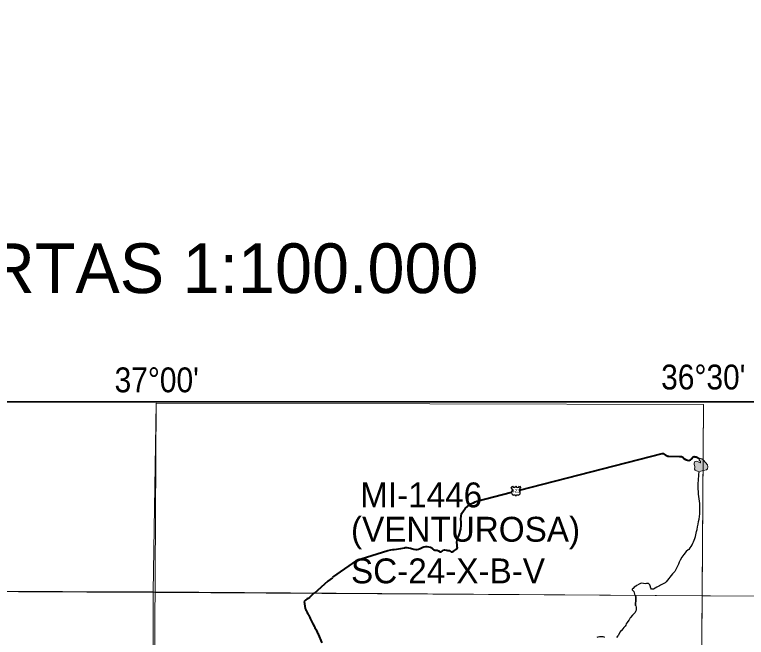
# Model space of a CAD drawing. Extents: x -1643653 to 4543381, y 1624270 to 13878484.
# Drawn here: x 604813 to 619526, y 8920034 to 8932559 of the extents above; entities that cross this region are included whole.
import ezdxf
from ezdxf.enums import TextEntityAlignment as Align

# ---------------------------------------------------------------- set-up
doc = ezdxf.new("R2010")
doc.units = 0
doc.header["$LTSCALE"] = 200
doc.layers.add('1', color=7, linetype='Continuous', lineweight=13)
doc.layers.add('6', color=7, linetype='Continuous', lineweight=13)

msp = doc.modelspace()

# ---------------------------------------------------------------- hatches: boundary and pattern name
at = {"layer": '6'}
msp.add_hatch(color=256, dxfattribs=at).paths.add_polyline_path([(618590.4, 8923622.6), (618579.9, 8923599.2), (618603.3, 8923569.1), (618601.9, 8923550), (618595.2, 8923541.4), (618555.1, 8923567.6), (618516.4, 8923579.6), (618490.1, 8923569.1), (618473.9, 8923540.4), (618479.6, 8923509.8), (618492, 8923472.6), (618488.2, 8923448.2), (618485.8, 8923418.6), (618496.8, 8923398.6), (618526.4, 8923383.3), (618561.3, 8923372.8), (618610, 8923374.2), (618666.8, 8923390.9), (618723.7, 8923405.7), (618745.6, 8923421), (618754.2, 8923461.6), (618742.3, 8923501.7), (618701.7, 8923551.9), (618664, 8923597.7), (618633.9, 8923625.4), (618610.5, 8923632.6)])

# ---------------------------------------------------------------- linework, layer by layer
at = {"layer": '1', "lineweight": 25}
msp.add_spline([(814781, 9009175.5), (814787.2, 9009173.4), (814796.9, 9009173.4), (814799.4, 9009172.4), (814805.1, 9009174.5), (814805.6, 9009176.5), (814811.7, 9009179.5), (814811.7, 9009179.5), (814801.5, 9009181), (814790.7, 9009181.5), (814784.1, 9009183.1), (814777.4, 9009185.1), (814778.4, 9009175.5)], degree=3, dxfattribs=at)
at = {"layer": '6', "lineweight": 25}
for p, q in [((614790.2, 8923043.1), (614822.1, 8923075.1)), ((614962, 8923075.1), (614994, 8923043.1))]:
    msp.add_line(p, q, dxfattribs=at)
at = {"layer": '6', "lineweight": 35}
msp.add_lwpolyline([(574695.3, 8924769.6), (626625.7, 8924769.6), (626625.7, 8896026.7), (574695.3, 8896026.7)], close=True, dxfattribs=at)
at = {"layer": '6'}
for points in [[(607657.7, 8924743.3), (607574.2, 8909874.9), (607492.3, 8896026.7)], [(618663, 8924716.1), (618558.3, 8909803.7), (618456.5, 8896026.7)], [(574684.9, 8921064.7), (596639.8, 8920989.8), (607636.3, 8920937.2), (626625.7, 8920820.5)]]:
    msp.add_lwpolyline(points, dxfattribs=at)
for points in [[(607657.7, 8924743.3), (618663, 8924716.1), (618636, 8920869.6), (607600.8, 8920952.4)], [(618590.4, 8923622.6), (618579.9, 8923599.2), (618603.3, 8923569.1), (618601.9, 8923550), (618595.2, 8923541.4), (618555.1, 8923567.6), (618516.4, 8923579.6), (618490.1, 8923569.1), (618473.9, 8923540.4), (618479.6, 8923509.8), (618492, 8923472.6), (618488.2, 8923448.2), (618485.8, 8923418.6), (618496.8, 8923398.6), (618526.4, 8923383.3), (618561.3, 8923372.8), (618610, 8923374.2), (618666.8, 8923390.9), (618723.7, 8923405.7), (618745.6, 8923421), (618754.2, 8923461.6), (618742.3, 8923501.7), (618701.7, 8923551.9), (618664, 8923597.7), (618633.9, 8923625.4), (618610.5, 8923632.6)], [(607600.8, 8920952.4), (596639.8, 8920989.8), (596608.8, 8909934.4), (607569.8, 8909894.9)], [(618636, 8920869.6), (626625.7, 8920820.5), (626625.7, 8909822.1), (618558.7, 8909851.2)]]:
    msp.add_lwpolyline(points, close=True, dxfattribs=at)
at = {"layer": '6', "lineweight": 40}
for points in [[(614964.2, 8922992.9), (617832.6, 8923732.6), (617846.7, 8923732.8), (617858.9, 8923730.9), (617871.2, 8923721), (617893.7, 8923707.2), (617921.3, 8923691.5), (617934.6, 8923682.6), (617949.8, 8923677.8), (617965, 8923676), (618178.8, 8923671.4), (618220.3, 8923669), (618246.8, 8923657.3), (618269.5, 8923633.4), (618301.1, 8923613.7), (618341.8, 8923600.2), (618367.2, 8923594.5), (618405.5, 8923607.3), (618420.6, 8923616.6), (618432.5, 8923630.9), (618446.4, 8923654.4), (618458.4, 8923663.7), (618473.5, 8923670), (618492.7, 8923668.3), (618517.1, 8923664.6), (618591.3, 8923622.3)], [(611214.5, 8921246.7), (611690.9, 8921581.7), (611739.2, 8921604.7), (611780.6, 8921615.4), (612315.8, 8921783.7), (612380.5, 8921791.8), (612418.8, 8921801.5), (612446.2, 8921801.9), (612579.5, 8921823.3), (612649.2, 8921836.5), (612665.4, 8921838.8), (612696.8, 8921839.3), (612734.3, 8921834.8), (612769.8, 8921828.3), (612794.3, 8921820.6), (612836.9, 8921811.2), (612878.6, 8921802.8), (612904.9, 8921800.2), (612931.2, 8921805.6), (612968.5, 8921819.4), (612991.5, 8921833.9), (613020.7, 8921847.5), (613043.9, 8921853.9), (613078.2, 8921864.6), (613100.5, 8921863.9), (613172.6, 8921848.9), (613187.9, 8921842.1), (613203.2, 8921832.2), (613213.5, 8921824.3), (613217.6, 8921816.3), (613223.8, 8921806.3), (613239.2, 8921795.4), (613263.6, 8921790.7), (613283.8, 8921790), (613306.2, 8921786.3), (613333.6, 8921777.7), (613370.4, 8921757.1), (613391.7, 8921751.3), (613410.8, 8921764.8), (613432.7, 8921788.4), (613459, 8921792.8), (613487.4, 8921786.2), (613506.7, 8921785.5), (613523.9, 8921782.7), (613547.3, 8921778.1), (613567.7, 8921770.3), (613590.2, 8921755.5), (613610.5, 8921752.8), (613631.6, 8921763.2), (613655.6, 8921783.8), (613674.6, 8921799.3), (613688.6, 8921808.6), (613703.7, 8921814.9), (613713.7, 8921824.2), (613717.6, 8921837.4), (613713.3, 8921852.5), (613712.8, 8921885.8), (613707.8, 8921948.4), (613715.8, 8922026.4), (613743.5, 8922073.3), (613761, 8922118.1), (613780.1, 8922192.2), (613785.2, 8922213.2), (613792, 8922289.4), (613792.2, 8922338.9), (613787.9, 8922425.8), (613790.3, 8922468.3), (613797.6, 8922523), (613826.5, 8922560.8), (613869.1, 8922624.2), (613980.1, 8922716.9), (614036.5, 8922740.1), (614074.7, 8922760.9), (614109.9, 8922772.6), (614804.5, 8922951.7)], [(611201.4, 8921234.4), (611108.7, 8921166), (610832.8, 8920916.1)], [(610827.8, 8920917.6), (610823, 8920914), (610762.1, 8920855.7), (610749.5, 8920841.5), (610740.9, 8920836.9), (610713, 8920816.2), (610698.2, 8920806.3), (610662.6, 8920780.4), (610653.5, 8920774.9), (610648.2, 8920770.6), (610634.6, 8920757.1)], [(610634.6, 8920757.1), (610655.2, 8920612.5), (610665.4, 8920591.1), (610678.2, 8920567.9), (610682, 8920558.9), (610694.4, 8920535.7), (610709.7, 8920504), (610719.3, 8920486.7), (610726, 8920471.9), (610739.4, 8920447.4), (610745.8, 8920433.2), (610758.2, 8920410.6), (610809.7, 8920308.8), (610840.7, 8920249.1), (610850, 8920232.8), (610852.7, 8920225.4), (610867.4, 8920199.1), (610898.1, 8920137.8), (610910.3, 8920115.9), (610916.7, 8920101.6), (610989.7, 8919925.2)]]:
    msp.add_lwpolyline(points, dxfattribs=at)
at = {"layer": '6', "lineweight": 25}
for points in [[(618385.8, 8921803.1), (618379.3, 8921802.6), (618357.2, 8921792.1), (618316.2, 8921761.1), (618268.5, 8921697.7), (618226.7, 8921644.5), (618197.2, 8921585.4), (618177.6, 8921543.6), (618164, 8921504), (618129.5, 8921438.8), (618113.7, 8921413.2), (618101.9, 8921385.8), (618086.1, 8921356.2), (618063.2, 8921330.6), (618043.2, 8921312), (617913, 8921148.2), (617895, 8921131.8), (617799.5, 8921081.7), (617778.4, 8921071.3), (617725.1, 8921044.2), (617655.8, 8921005.7), (617632.6, 8921001.2), (617620.5, 8921001), (617607, 8921022.1), (617592.1, 8921070.3), (617586.7, 8921090.5), (617572.3, 8921107.4), (617556, 8921116.3), (617517.5, 8921115.6), (617491.2, 8921112.2), (617455.8, 8921114.7), (617418.2, 8921122.1), (617400, 8921119.8), (617381.9, 8921110.4), (617345.8, 8921092.5)], [(617334.2, 8921086.1), (617270.4, 8921047), (617247.5, 8921019.3), (617230.5, 8921004.9), (617231.8, 8920988.8), (617263.7, 8920954.9), (617272.2, 8920926.8), (617283, 8920878)], [(617303, 8920665.4), (617309.3, 8920639.1), (617311.5, 8920622.3), (617313.5, 8920613.9), (617313.6, 8920598.5), (617309.4, 8920583), (617298.1, 8920552.1), (617290.2, 8920537.8), (617278.2, 8920522.3), (617239.5, 8920482.6), (617196.2, 8920435), (617188.5, 8920425.5), (617182.5, 8920416.2), (617169.7, 8920388.5), (617163.2, 8920380.5), (617127.8, 8920330.6), (617112.8, 8920304.9), (617101.5, 8920282.3), (617087.7, 8920260.7), (617065.5, 8920231.4), (617042.8, 8920204.7), (617013.1, 8920175.2), (617003.5, 8920164.7), (616988.6, 8920143.8), (616945.6, 8920070.1), (616939.6, 8920064.2), (616914.7, 8920032.8)], [(616683.6, 8920028.8), (616669.3, 8920035.2), (616647.7, 8920042.1), (616635, 8920043.9), (616602.2, 8920045.9), (616583.8, 8920046.3), (616574.1, 8920045.7), (616539, 8920038.2), (616523, 8920032.3)]]:
    msp.add_lwpolyline(points, dxfattribs=at)
at = {"layer": '6', "lineweight": 35}
msp.add_lwpolyline([(617294.2, 8920878.4), (617302.4, 8920840.9), (617306.5, 8920803.1), (617306.1, 8920783.9), (617304, 8920766.2), (617295.2, 8920713.2), (617295.4, 8920693.6), (617300.5, 8920675.8), (617303, 8920665.4)], dxfattribs=at)
at = {"layer": '6', "lineweight": 25}
for centre, radius, start, end in [((614777.7, 8922998.7), 46.1, 317.5721, 74.36886), ((614848.4, 8922941.7), 44.9, 144.73733, 264.65778), ((614857.1, 8923088.5), 37.4, 200.95927, 339.04073), ((614927, 8923088.5), 37.4, 200.95927, 339.04073), ((614935.7, 8922941.7), 44.9, 275.34222, 35.26267), ((615006.4, 8922998.7), 46.1, 105.62774, 222.4279), ((614844, 8922779), 118, 72.89371, 89.90057), ((614873.2, 8922873.7), 18.9, 357.69345, 72.92955), ((614910.9, 8922873.7), 18.9, 107.07045, 182.30655), ((614940.1, 8922779), 118, 90.09943, 107.10629)]:
    msp.add_arc(centre, radius, start, end, dxfattribs=at)
msp.add_spline([(618379.3, 8921802.6), (618451, 8921925.6), (618534.6, 8922201.8), (618593.2, 8922628.5), (618559.7, 8923013.4), (618576.4, 8923356.4)], degree=3, dxfattribs=at)

# ---------------------------------------------------------------- texts
at = {"layer": '6'}
msp.add_text('ARTICULAÇÃO DAS CARTAS 1:100.000', height=1000, dxfattribs=at).set_placement((601765.5, 8926958.2), align=Align.CENTER)
for s, height, width, p in [("37°00'", 500, 0.9, (607670.1, 8924963.2)), ("36°30'", 500, 0.9, (618660.1, 8925020.1)), ('423', 70, 0.75, (614892.5, 8922945.5))]:
    msp.add_text(s, height=height, dxfattribs=dict(at, width=width)).set_placement(p, align=Align.CENTER)
for s, p in [('MI-1446', (611760.8, 8922649.4)), ('(VENTUROSA)', (611576.4, 8921958.6)), ('SC-24-X-B-V', (611576.4, 8921121.5))]:
    msp.add_text(s, height=500, dxfattribs=at).set_placement(p)

doc.saveas('drawing.dxf')
